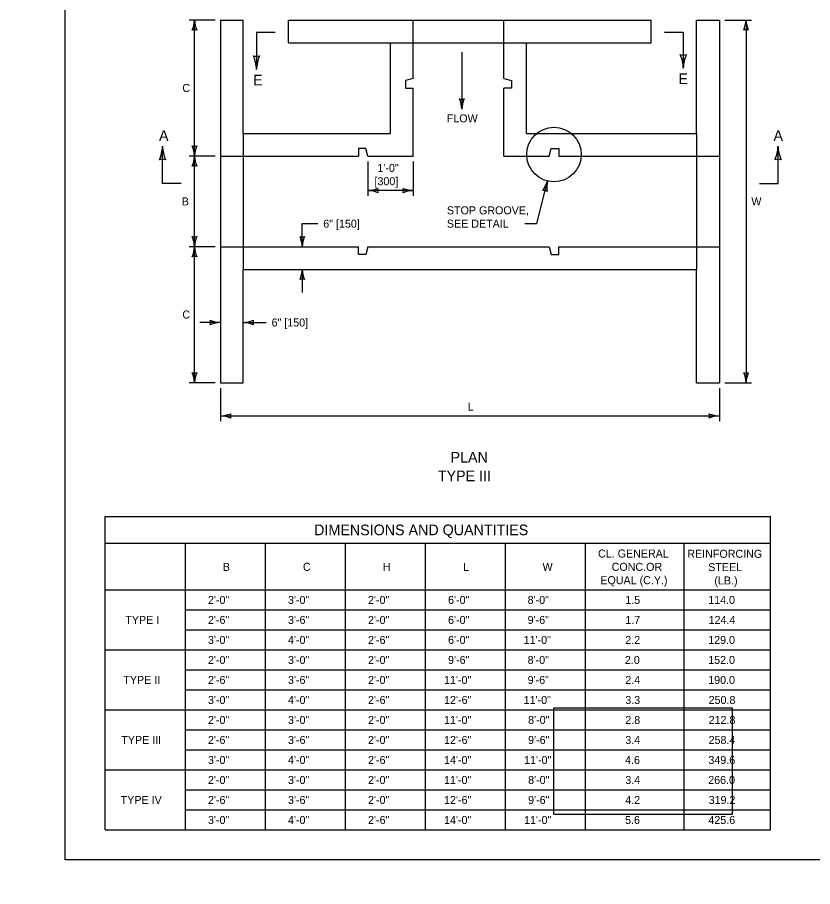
# Model space of a CAD drawing. Extents: x 49991.4 to 50021, y 49987.6 to 50011.4.
# Drawn here: x 49999.02 to 50004.99, y 49987.6 to 49994.12 of the extents above; entities that cross this region are included whole.
import ezdxf

# ---------------------------------------------------------------- set-up
doc = ezdxf.new("R2010")
doc.units = 0
for name, color, linetype in [('Level 1', 7, 'Continuous'), ('Level 2', 7, 'Continuous'), ('Level 3', 7, 'Continuous'), ('Level 4', 7, 'Continuous'), ('Level 6', 7, 'Continuous')]:
    doc.layers.add(name, color=color, linetype=linetype)

msp = doc.modelspace()

# ---------------------------------------------------------------- linework, layer by layer
at = {"layer": 'Level 1'}
for p, q in [((50000.5469, 49994.0962), (50000.5469, 49991.3762)), ((50000.5469, 49994.0962), (50000.7169, 49994.0962)), ((50000.7169, 49993.2461), (50000.7169, 49994.0962)), ((50001.0569, 49994.0962), (50003.7768, 49994.0962)), ((50001.0569, 49993.9262), (50001.0569, 49994.0962)), ((50001.9918, 49993.6571), (50001.9918, 49994.0962)), ((50002.6718, 49993.6571), (50002.6718, 49994.0962)), ((50003.7768, 49993.9262), (50003.7768, 49994.0962)), ((50004.1168, 49994.0962), (50004.2868, 49994.0962)), ((50004.1168, 49993.2461), (50004.1168, 49994.0962)), ((50004.2868, 49994.0962), (50004.2868, 49991.3762)), ((50001.0569, 49993.9262), (50001.8218, 49993.9262)), ((50001.8218, 49993.2461), (50001.8218, 49993.9262)), ((50002.8418, 49993.2461), (50002.8418, 49993.9262)), ((50002.8418, 49993.9262), (50003.7768, 49993.9262)), ((50001.9918, 49993.6571), (50001.9351, 49993.643)), ((50001.9351, 49993.643), (50001.9351, 49993.5863)), ((50002.6718, 49993.6571), (50002.7285, 49993.6429)), ((50002.7285, 49993.6429), (50002.7285, 49993.5863)), ((50001.9351, 49993.5863), (50001.9918, 49993.5863)), ((50001.9918, 49993.0761), (50001.9918, 49993.5863)), ((50002.6718, 49993.0761), (50002.6718, 49993.5863)), ((50002.7285, 49993.5863), (50002.6718, 49993.5863)), ((50000.7169, 49993.2461), (50001.8218, 49993.2461)), ((50002.8418, 49993.2461), (50004.1168, 49993.2461)), ((50001.6377, 49993.1328), (50001.581, 49993.1328)), ((50001.581, 49993.1328), (50001.581, 49993.0761)), ((50001.6518, 49993.0761), (50001.6377, 49993.1328)), ((50003.0118, 49993.0761), (50003.026, 49993.1328)), ((50003.026, 49993.1328), (50003.0826, 49993.1328)), ((50003.0826, 49993.1328), (50003.0826, 49993.0761)), ((50000.5469, 49993.0761), (50001.581, 49993.0761)), ((50001.6518, 49993.0761), (50001.9918, 49993.0761)), ((50002.6718, 49993.0761), (50003.0118, 49993.0761)), ((50003.0826, 49993.0761), (50004.2868, 49993.0761)), ((50000.5469, 49992.3962), (50001.581, 49992.3962)), ((50001.581, 49992.3395), (50001.581, 49992.3962)), ((50001.6518, 49992.3962), (50001.6377, 49992.3395)), ((50001.6518, 49992.3962), (50003.0118, 49992.3962)), ((50003.0118, 49992.3962), (50003.026, 49992.3395)), ((50003.0826, 49992.3395), (50003.0826, 49992.3962)), ((50003.0826, 49992.3962), (50004.2868, 49992.3962)), ((50001.6377, 49992.3395), (50001.581, 49992.3395)), ((50003.026, 49992.3395), (50003.0826, 49992.3395)), ((50000.7169, 49992.2262), (50004.1168, 49992.2262)), ((50000.7169, 49991.3762), (50000.7169, 49992.2262)), ((50004.1168, 49991.3762), (50004.1168, 49992.2262)), ((50000.5469, 49991.3762), (50000.7169, 49991.3762)), ((50004.1168, 49991.3762), (50004.2868, 49991.3762)), ((49999.0245, 49987.5988), (49999.0245, 49987.5988))]:
    msp.add_line(p, q, dxfattribs=at)
msp.add_lwpolyline([(49999.3835, 49998.9992), (50016.7501, 49998.9992), (50016.7501, 49987.7988), (49999.3835, 49987.7988)], close=True, dxfattribs=at)
at = {"layer": 'Level 2'}
for p, q in [((49999.6837, 49990.3734), (50004.6694, 49990.3734)), ((49999.6837, 49988.0234), (49999.6837, 49990.3734)), ((50004.6694, 49988.0234), (50004.6694, 49990.3734)), ((49999.6837, 49990.1734), (50004.6694, 49990.1734)), ((50000.2837, 49988.0234), (50000.2837, 49990.1734)), ((50000.8837, 49988.0234), (50000.8837, 49990.1734)), ((50001.4837, 49988.0234), (50001.4837, 49990.1734)), ((50002.0837, 49988.0234), (50002.0837, 49990.1734)), ((50002.6837, 49988.0234), (50002.6837, 49990.1734)), ((50003.2837, 49988.0234), (50003.2837, 49990.1734)), ((50004.0223, 49988.0234), (50004.0223, 49990.1734)), ((49999.6837, 49989.8234), (50004.6694, 49989.8234)), ((50000.2837, 49989.6734), (50004.6694, 49989.6734)), ((50000.2837, 49989.5234), (50004.6694, 49989.5234)), ((49999.6837, 49989.3734), (50004.6694, 49989.3734)), ((50000.2837, 49989.2234), (50004.6694, 49989.2234)), ((50000.2837, 49989.0734), (50004.6694, 49989.0734)), ((49999.6837, 49988.9234), (50004.6694, 49988.9234)), ((50000.2837, 49988.7734), (50004.6694, 49988.7734)), ((50000.2837, 49988.6234), (50004.6694, 49988.6234)), ((49999.6837, 49988.4734), (50004.6694, 49988.4734)), ((50000.2837, 49988.3234), (50004.6256, 49988.3234)), ((50000.2837, 49988.3234), (50004.6694, 49988.3234)), ((50000.2837, 49988.1734), (50004.6694, 49988.1734)), ((49999.6837, 49988.0234), (50004.6694, 49988.0234))]:
    msp.add_line(p, q, dxfattribs=at)
msp.add_lwpolyline([(50003.0458, 49988.9397), (50004.3823, 49988.9397), (50004.3823, 49988.1387), (50003.0458, 49988.1387)], close=True, dxfattribs=at)
at = {"layer": 'Level 3'}
for p, q in [((50000.5069, 49994.0962), (50000.3123, 49994.0962)), ((50000.3523, 49991.3762), (50000.3523, 49994.0962)), ((50004.3268, 49994.0962), (50004.5268, 49994.0962)), ((50004.4868, 49994.0962), (50004.4868, 49991.3762)), ((50002.3565, 49993.8547), (50002.3565, 49993.4293)), ((50000.5069, 49993.0761), (50000.3123, 49993.0761)), ((50001.6518, 49993.0361), (50001.6518, 49992.7776)), ((50001.9918, 49993.0361), (50001.9918, 49992.7776)), ((50002.9189, 49992.5696), (50002.9981, 49992.889)), ((50001.9918, 49992.8176), (50001.6518, 49992.8176)), ((50001.1602, 49992.5696), (50001.2775, 49992.5696)), ((50001.1602, 49992.3962), (50001.1602, 49992.5696)), ((50002.8283, 49992.5696), (50002.9189, 49992.5696)), ((50000.5069, 49992.3962), (50000.3123, 49992.3962)), ((50001.1602, 49992.2262), (50001.1602, 49992.0528)), ((50000.5469, 49991.8285), (50000.3923, 49991.8285)), ((50000.7169, 49991.8285), (50000.8903, 49991.8285)), ((50000.5069, 49991.3762), (50000.3123, 49991.3762)), ((50000.5469, 49991.3362), (50000.5469, 49991.0881)), ((50004.2868, 49991.3362), (50004.2868, 49991.0881)), ((50004.3268, 49991.3762), (50004.5268, 49991.3762)), ((50000.5469, 49991.1281), (50004.2868, 49991.1281))]:
    msp.add_line(p, q, dxfattribs=at)
msp.add_circle((50003.0473, 49993.0876), 0.2046, dxfattribs=at)
for centre, radius, start, end in [((50000.1196, 49994.1077), 0.233, 337.92284, 357.17269), ((50000.5744, 49994.1054), 0.2223, 182.36048, 202.54399), ((50004.2541, 49994.1077), 0.233, 337.92284, 357.17269), ((50004.7089, 49994.1054), 0.2223, 182.36048, 202.54399), ((50000.3523, 49993.968), 0.0548, 72.13882, 107.86118), ((50004.4868, 49993.968), 0.0548, 72.13882, 107.86118), ((50000.5207, 49993.714), 0.2964, 2.36048, 22.54399), ((50000.8169, 49993.8972), 0.073, 252.13882, 287.86118), ((50001.1272, 49993.7109), 0.3107, 157.92284, 177.17269), ((50003.7206, 49993.7233), 0.2964, 2.36048, 22.54399), ((50004.0168, 49993.9065), 0.073, 252.13882, 287.86118), ((50004.3271, 49993.7202), 0.3107, 157.92284, 177.17269), ((50002.1344, 49993.4201), 0.2223, 2.36048, 22.54399), ((50002.3565, 49993.5575), 0.0548, 252.13882, 287.86118), ((50002.5892, 49993.4178), 0.233, 157.92284, 177.17269), ((50000.1302, 49993.0669), 0.2223, 2.36048, 22.54399), ((50000.3523, 49993.2043), 0.0548, 252.13882, 287.86118), ((50000.585, 49993.0646), 0.233, 157.92284, 177.17269), ((49999.8161, 49993.1624), 0.2964, 337.45601, 357.63952), ((50000.4226, 49993.1655), 0.3107, 182.82731, 202.07716), ((50004.4165, 49993.1655), 0.3107, 337.92284, 357.17269), ((50005.023, 49993.1624), 0.2964, 182.36048, 202.54399), ((50000.1123, 49992.9792), 0.073, 72.13882, 107.86118), ((50000.1196, 49993.0876), 0.233, 337.92284, 357.17269), ((50000.5744, 49993.0853), 0.2223, 182.36048, 202.54399), ((50004.7268, 49992.9792), 0.073, 72.13882, 107.86118), ((50000.3523, 49992.9479), 0.0548, 72.13882, 107.86118), ((50001.6426, 49993.0397), 0.2223, 272.36048, 292.54399), ((50001.78, 49992.8176), 0.0548, 162.13882, 197.86118), ((50001.8636, 49992.8176), 0.0548, 342.13882, 17.86118), ((50002.0033, 49993.0503), 0.233, 247.92284, 267.17269), ((50002.775, 49992.9561), 0.233, 323.99561, 343.24546), ((50003.2159, 49992.8444), 0.2223, 168.43325, 188.61676), ((50001.6403, 49992.5849), 0.233, 67.92284, 87.17269), ((50002.001, 49992.5955), 0.2223, 92.36048, 112.54399), ((50002.9672, 49992.7645), 0.0548, 58.21159, 93.93395), ((50000.1302, 49992.387), 0.2223, 2.36048, 22.54399), ((50000.3523, 49992.5244), 0.0548, 252.13882, 287.86118), ((50000.585, 49992.3847), 0.233, 157.92284, 177.17269), ((50000.9381, 49992.387), 0.2223, 2.36048, 22.54399), ((50001.1602, 49992.5244), 0.0548, 252.13882, 287.86118), ((50001.3929, 49992.3847), 0.233, 157.92284, 177.17269), ((50000.1196, 49992.4077), 0.233, 337.92284, 357.17269), ((50000.5744, 49992.4054), 0.2223, 182.36048, 202.54399), ((50000.3523, 49992.268), 0.0548, 72.13882, 107.86118), ((50000.9275, 49992.2377), 0.233, 337.92284, 357.17269), ((50001.3823, 49992.2354), 0.2223, 182.36048, 202.54399), ((50001.1602, 49992.098), 0.0548, 72.13882, 107.86118), ((50000.4187, 49991.8285), 0.0548, 342.13882, 17.86118), ((50000.5584, 49992.0612), 0.233, 247.92284, 267.17269), ((50000.5561, 49991.6064), 0.2223, 92.36048, 112.54399), ((50000.7077, 49992.0506), 0.2223, 272.36048, 292.54399), ((50000.7054, 49991.5958), 0.233, 67.92284, 87.17269), ((50000.8451, 49991.8285), 0.0548, 162.13882, 197.86118), ((50000.1302, 49991.367), 0.2223, 2.36048, 22.54399), ((50000.3523, 49991.5044), 0.0548, 252.13882, 287.86118), ((50000.585, 49991.3647), 0.233, 157.92284, 177.17269), ((50004.2647, 49991.367), 0.2223, 2.36048, 22.54399), ((50004.4868, 49991.5044), 0.0548, 252.13882, 287.86118), ((50004.7195, 49991.3647), 0.233, 157.92284, 177.17269), ((50000.5377, 49991.3502), 0.2223, 272.36048, 292.54399), ((50000.6751, 49991.1281), 0.0548, 162.13882, 197.86118), ((50004.1586, 49991.1281), 0.0548, 342.13882, 17.86118), ((50004.2983, 49991.3608), 0.233, 247.92284, 267.17269), ((50000.5354, 49990.8954), 0.233, 67.92284, 87.17269), ((50004.296, 49990.906), 0.2223, 92.36048, 112.54399)]:
    msp.add_arc(centre, radius, start, end, dxfattribs=at)
at = {"layer": 'Level 4'}
for p, q in [((50001.8218, 49993.9262), (50002.8418, 49993.9262)), ((50000.7169, 49993.2461), (50000.7169, 49992.2262)), ((50004.1168, 49993.2461), (50004.1168, 49992.2262))]:
    msp.add_line(p, q, dxfattribs=at)
at = {"layer": 'Level 6'}
for p, q in [((50000.8169, 49994.0063), (50000.9569, 49994.0063)), ((50000.8169, 49994.0063), (50000.8169, 49993.7263)), ((50003.8768, 49994.0063), (50004.0168, 49994.0063)), ((50004.0168, 49994.0063), (50004.0168, 49993.7355)), ((50000.1123, 49992.8702), (50000.1123, 49993.1502)), ((50004.7268, 49992.8702), (50004.7268, 49993.1502)), ((50000.2523, 49992.8702), (50000.1123, 49992.8702)), ((50004.5868, 49992.8702), (50004.7268, 49992.8702))]:
    msp.add_line(p, q, dxfattribs=at)

# ---------------------------------------------------------------- texts
at = {"layer": 'Level 2'}
for s, height, p in [('E', 0.0799, (50000.7924, 49993.6063)), ('E', 0.0799, (50003.9795, 49993.6156)), ('C', 0.06, (50000.2613, 49993.5567)), ('FLOW', 0.06, (50002.2434, 49993.3293)), ('A', 0.08, (50000.0862, 49993.1902)), ('A', 0.08, (50004.6925, 49993.1902)), ('1\'-0"', 0.06, (50001.7234, 49992.9576)), ('[300]', 0.06, (50001.7016, 49992.8576)), ('B', 0.06, (50000.2568, 49992.7062)), ('W', 0.06, (50004.5268, 49992.7062)), ('STOP GROOVE,', 0.06, (50002.2443, 49992.6396)), ('6" [150]', 0.06, (50001.3175, 49992.5396)), ('SEE DETAIL', 0.06, (50002.2443, 49992.5396)), ('C', 0.06, (50000.2613, 49991.8583)), ('6" [150]', 0.06, (50000.9303, 49991.7985)), ('L', 0.06, (50002.3999, 49991.1681)), ('PLAN', 0.08, (50002.272, 49990.7781)), ('TYPE III', 0.08, (50002.1766, 49990.6381)), ('DIMENSIONS AND QUANTITIES', 0.08, (50001.2495, 49990.2334)), ('CL. GENERAL', 0.06, (50003.3774, 49990.0664)), ('REINFORCING', 0.06, (50004.0466, 49990.0643)), ('B', 0.06, (50000.5651, 49989.9664)), ('C', 0.06, (50001.1651, 49989.9664)), ('H', 0.06, (50001.7641, 49989.9664)), ('L', 0.06, (50002.3667, 49989.9664)), ('W', 0.06, (50002.9615, 49989.9664)), ('CONC.OR ', 0.06, (50003.4794, 49989.9664)), ('STEEL', 0.06, (50004.2035, 49989.9643)), ('EQUAL (C.Y.)', 0.06, (50003.3947, 49989.8664)), ('(LB.)', 0.06, (50004.2497, 49989.8643)), ('2\'-0"', 0.06, (50000.4531, 49989.7184)), ('3\'-0"', 0.06, (50001.0531, 49989.7184)), ('2\'-0"', 0.06, (50001.6531, 49989.7184)), ('6\'-0"', 0.06, (50002.2531, 49989.7184)), ('8\'-0"', 0.06, (50002.8497, 49989.7184)), ('1.5', 0.06, (50003.5817, 49989.7184)), ('114.0', 0.06, (50004.2035, 49989.7184)), ('TYPE I', 0.06, (49999.8337, 49989.5684)), ('2\'-6"', 0.06, (50000.4531, 49989.5684)), ('3\'-6"', 0.06, (50001.0531, 49989.5684)), ('2\'-0"', 0.06, (50001.6531, 49989.5684)), ('6\'-0"', 0.06, (50002.2531, 49989.5684)), ('9\'-6"', 0.06, (50002.8497, 49989.5684)), ('1.7', 0.06, (50003.5817, 49989.5684)), ('124.4', 0.06, (50004.2065, 49989.5684)), ('3\'-0"', 0.06, (50000.4531, 49989.4184)), ('4\'-0"', 0.06, (50001.0531, 49989.4184)), ('2\'-6"', 0.06, (50001.6531, 49989.4184)), ('6\'-0"', 0.06, (50002.2531, 49989.4184)), ('11\'-0"', 0.06, (50002.8197, 49989.4184)), ('2.2', 0.06, (50003.5817, 49989.4184)), ('129.0', 0.06, (50004.2035, 49989.4184)), ('2\'-0"', 0.06, (50000.4531, 49989.2684)), ('3\'-0"', 0.06, (50001.0531, 49989.2684)), ('2\'-0"', 0.06, (50001.6531, 49989.2684)), ('9\'-6"', 0.06, (50002.2531, 49989.2684)), ('8\'-0"', 0.06, (50002.8497, 49989.2684)), ('2.0', 0.06, (50003.5787, 49989.2684)), ('152.0', 0.06, (50004.2035, 49989.2684)), ('TYPE II', 0.06, (49999.8186, 49989.1184)), ('2\'-6"', 0.06, (50000.4531, 49989.1184)), ('3\'-6"', 0.06, (50001.0531, 49989.1184)), ('2\'-0"', 0.06, (50001.6531, 49989.1184)), ('11\'-0"', 0.06, (50002.2231, 49989.1184)), ('9\'-6"', 0.06, (50002.8497, 49989.1184)), ('2.4', 0.06, (50003.5817, 49989.1184)), ('190.0', 0.06, (50004.2035, 49989.1184)), ('3\'-0"', 0.06, (50000.4531, 49988.9684)), ('4\'-0"', 0.06, (50001.0531, 49988.9684)), ('2\'-6"', 0.06, (50001.6531, 49988.9684)), ('12\'-6"', 0.06, (50002.2231, 49988.9684)), ('11\'-0"', 0.06, (50002.8197, 49988.9684)), ('3.3', 0.06, (50003.5817, 49988.9684)), ('250.8', 0.06, (50004.2065, 49988.9684)), ('2\'-0"', 0.06, (50000.4531, 49988.8184)), ('3\'-0"', 0.06, (50001.0531, 49988.8184)), ('2\'-0"', 0.06, (50001.6531, 49988.8184)), ('11\'-0"', 0.06, (50002.2231, 49988.8184)), ('8\'-0"', 0.06, (50002.8531, 49988.8184)), ('2.8', 0.06, (50003.5817, 49988.8184)), ('212.8', 0.06, (50004.2065, 49988.8184)), ('TYPE III', 0.06, (49999.8035, 49988.6684)), ('2\'-6"', 0.06, (50000.4531, 49988.6684)), ('3\'-6"', 0.06, (50001.0531, 49988.6684)), ('2\'-0"', 0.06, (50001.6531, 49988.6684)), ('12\'-6"', 0.06, (50002.2231, 49988.6684)), ('9\'-6"', 0.06, (50002.8531, 49988.6684)), ('3.4', 0.06, (50003.5817, 49988.6684)), ('258.4', 0.06, (50004.2065, 49988.6684)), ('3\'-0"', 0.06, (50000.4531, 49988.5184)), ('4\'-0"', 0.06, (50001.0531, 49988.5184)), ('2\'-6"', 0.06, (50001.6531, 49988.5184)), ('14\'-0"', 0.06, (50002.2231, 49988.5184)), ('11\'-0"', 0.06, (50002.8231, 49988.5184)), ('4.6', 0.06, (50003.5801, 49988.5184)), ('349.6', 0.06, (50004.2049, 49988.5184)), ('2\'-0"', 0.06, (50000.4531, 49988.3684)), ('3\'-0"', 0.06, (50001.0531, 49988.3684)), ('2\'-0"', 0.06, (50001.6531, 49988.3684)), ('11\'-0"', 0.06, (50002.2231, 49988.3684)), ('8\'-0"', 0.06, (50002.8531, 49988.3684)), ('3.4', 0.06, (50003.5817, 49988.3684)), ('266.0', 0.06, (50004.2035, 49988.3684)), ('TYPE IV', 0.06, (49999.799, 49988.2184)), ('2\'-6"', 0.06, (50000.4531, 49988.2184)), ('3\'-6"', 0.06, (50001.0531, 49988.2184)), ('2\'-0"', 0.06, (50001.6531, 49988.2184)), ('12\'-6"', 0.06, (50002.2231, 49988.2184)), ('9\'-6"', 0.06, (50002.8531, 49988.2184)), ('4.2', 0.06, (50003.5817, 49988.2184)), ('319.2', 0.06, (50004.2065, 49988.2184)), ('3\'-0"', 0.06, (50000.4531, 49988.0684)), ('4\'-0"', 0.06, (50001.0531, 49988.0684)), ('2\'-6"', 0.06, (50001.6531, 49988.0684)), ('14\'-0"', 0.06, (50002.2231, 49988.0684)), ('11\'-0"', 0.06, (50002.8231, 49988.0684)), ('5.6', 0.06, (50003.5801, 49988.0684)), ('425.6', 0.06, (50004.2049, 49988.0684))]:
    msp.add_text(s, height=height, dxfattribs=at).set_placement(p)

doc.saveas('drawing.dxf')
